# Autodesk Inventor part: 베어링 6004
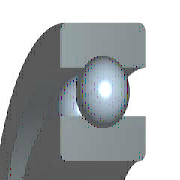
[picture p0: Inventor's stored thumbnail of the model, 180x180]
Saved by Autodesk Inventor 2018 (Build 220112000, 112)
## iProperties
IsCustomPart: 1
Created: 2012-02
Part Number: 베어링 6004
Material: 강철, 연강
Description: 깊은 그루브 볼 베어링
Document SubType Name: Modeling
Standard: KS B 2023
Designer: mduedu
Standards Organization: KS
Language: ko-KR
Size Designation: 6004 - 20 x 42 x 12
Categories: <MemberInstance><Categories><Category DisplayName="샤프트 부품" InternalName="7f7aeb1f-a693-4053-b835-cee3144e0d98" Mnemonic="SHFT"><Category DisplayName="베어링" Inter
Density: 7.85 g/cm^3
Appearance: 노란색
Mass: 68.2267 g
Surface Area: 70.0178 cm^2
Volume: 8.6913 cm^3
Author: mduedu
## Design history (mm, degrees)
sketch "스케치" dims "d0" = 5.72 (= -0.26 x WD + 0.26 x BD)
  geometry: L1 (3.14, 15.5)-(8.86, 15.5); L2 (6, 15.5)-(6, 12.64); L3 (6, 15.5)-(6, 18.36); L4 (3.875, 13.586)-(0, 13.586); L5 (0, 10)-(12, 10); L6 (3.875, 17.414)-(0, 17.414); L7 (0, 21)-(12, 21); L8 (12, 10)-(12, 13.586); L9 (8.125, 13.586)-(12, 13.586); L10 (8.125, 17.414)-(12, 17.414); L11 (12, 21)-(12, 17.414); L12 (-1.4, 0)-(8.4, 0) reference; L13 (0, -0.3)-(0, 5.3) reference
  constraints: 22 end point, 4 point on line, 2 collinear, 2 perpendicular, 2 symmetric about line, 1 midpoint, 1 parallel, 14 other
  dimensions: "d9" = 20 diameter of L5 L12 (= WD); "d11" = 42 diameter of L7 L12 (= BD); "d12" = 12 distance between parallel lines of L8 L13 (= KB); "d13" = 27.172 diameter of L9 L12 (= 0.326 x BD + 0.674 x WD)
revolve "본체" stored, may be unused: angle "d6" = 90 deg
revolve "볼" stored, may be unused: angle "d7" = 90 deg
pattern_circular "IDS_ARRAYBALL[SIMPL:T]" dims angle "d3" = 360 deg
body "Solid1"
fillet "모깎기1" dims "d1" = 0.6 (= KRS)
other parameters: "WD" = 20 [user parameter; used in 5 equation terms], "BD" = 42 [user parameter; used in 5 equation terms], "KB" = 12 [user parameter; used in 1 equation term], "KRS" = 0.6 [user parameter; used in 1 equation term], "d4" = 0, "d5" = 0, "d8" = 0, "d14" = 0, "d15" = 0, "BBA" = 0 [user parameter], "BC0" = 5000000 [user parameter], "BC" = 9360000 [user parameter], "BR" = 21 (= 0.5 x BD) [user parameter]
